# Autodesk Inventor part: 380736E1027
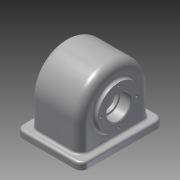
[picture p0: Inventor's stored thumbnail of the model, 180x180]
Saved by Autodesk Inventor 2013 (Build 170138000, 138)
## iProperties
Created: 2018-07
Part Number: 380736E1027
Material: 11111
Document SubType Name: Modeling
Designer: 05-01
Density: 7 g/cm^3
Mass: 2358.98 g
Surface Area: 768.537 cm^2
Volume: 336.996 cm^3
Author: 05-01
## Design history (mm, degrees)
sketch "스케치1"
  geometry: L1 (-51, 0)-(51, 0); L2 (51, 0)-(51, -50); L3 (51, -50)-(-51, -50); L4 (-51, -50)-(-51, 0); A1 r 51 centre (0, 0) between (51, 0) and (-51, 0); 1 further point
  constraints: 8 end point, 2 parallel, 2 point on circle, 2 tangent, 1 centre point, 1 coincident, 1 horizontal, 1 horizontal alignment, 1 perpendicular
  dimensions: "d0" = 102 diameter of A1; "d2" = 101 dimension on A1 L3
extrude "돌출1" new body sketch "스케치1" stored distance "d3" = 74; taper "d4" = 0 deg
fillet "모깎기1" dims "d5" = 12
feature "쉘1" dims "d6" = 9
sketch "스케치2"
  geometry: C1 r 31 at (0, 0); A1 r 39 centre (0, 0) between (0, 39) and (0, -39) reference
  constraints: 1 centre point, 1 coincident
  dimensions: "d7" = 62 diameter of C1
extrude "돌출2" join sketch "스케치2" distance "d9" = 5; taper "d10" = 0 deg
sketch "스케치3"
  geometry: C1 r 31 at (0, 0) reference; C2 r 31 at (0, 0) reference
extrude "돌출3" join sketch "스케치3" distance "d11" = 20; taper "d12" = 0 deg
hole "구멍1" diameter "d15" = 29; stored, may be unused: countersink angle "d19" = 90 deg, drill point angle "d21" = 118 deg; dims "d16" = 6, "d17" = 35, "d18" = 15, "d20" = 30, "d22" = 10, "d23" = 10
hole "구멍2" diameter "d26" = 36; stored, may be unused: countersink angle "d30" = 90 deg, drill point angle "d32" = 118 deg; dims "d24" = 10, "d25" = 10, "d27" = 6, "d28" = 42, "d29" = 15, "d31" = 25
sketch "스케치4"
  geometry: L1 (50, 0)-(0, 0) reference; L2 (-12, -90)-(-12, -12) reference; L3 (50, -102)-(0, -102) reference; L4 (62, -12)-(62, -90) reference; L5 (-22.5, 9)-(72.5, 9); L6 (72.5, 9)-(72.5, -111); L7 (72.5, -111)-(-22.5, -111); L8 (-22.5, -111)-(-22.5, 9); A1 r 12 centre (50, -12) between (62, -12) and (50, 0) reference; A2 r 12 centre (0, -12) between (0, 0) and (-12, -12) reference; A3 r 12 centre (0, -90) between (-12, -90) and (0, -102) reference; A4 r 12 centre (50, -90) between (50, -102) and (62, -90) reference; 3 further points
  constraints: 8 end point, 2 midpoint, 2 parallel, 1 horizontal, 1 horizontal alignment, 1 perpendicular, 1 vertical alignment
  dimensions: "d33" = 95 distance of L6.end L7.end; "d35" = 120 distance of L5.end L6.end
extrude "돌출4" join sketch "스케치4" distance "d36" = 10; taper "d37" = 0 deg
sketch "스케치5"
  geometry: C1 r 17.5 at (0, 0) reference; 1 further point
  constraints: 1 vertical alignment
  dimensions: "d38" = 26 distance of point (0, 26) C1.centre
hole "구멍3" sketch "스케치5" at (0, 26) diameter "d39" = 3.242; stored, may be unused: countersink angle "d43" = 90 deg, drill point angle "d45" = 118 deg; dims "d40" = 8, "d41" = 42, "d42" = 15, "d44" = 10
fillet "모깎기2" dims "d49" = 10
fillet "모깎기3" dims "d50" = 3
fillet "모깎기4" dims "d51" = 3
chamfer "모따기1" distance "d52" = 1; stored, may be unused: second distance "d53" = 2, angle "d54" = 45 deg
node "솔리드1"
mirror "대칭1"
pattern_circular "원형 패턴1" dims angle "d47" = 360 deg
mirror "대칭2"
node "절단 모서리 투영1"
